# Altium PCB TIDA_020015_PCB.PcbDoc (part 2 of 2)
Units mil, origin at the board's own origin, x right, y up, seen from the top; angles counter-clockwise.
Board outline 1470 x 1510 mil, 2 copper layers (Top Layer, Bottom Layer), stack 62 mil thick; 90 components, 41 nets, 222 pads, 53 vias.
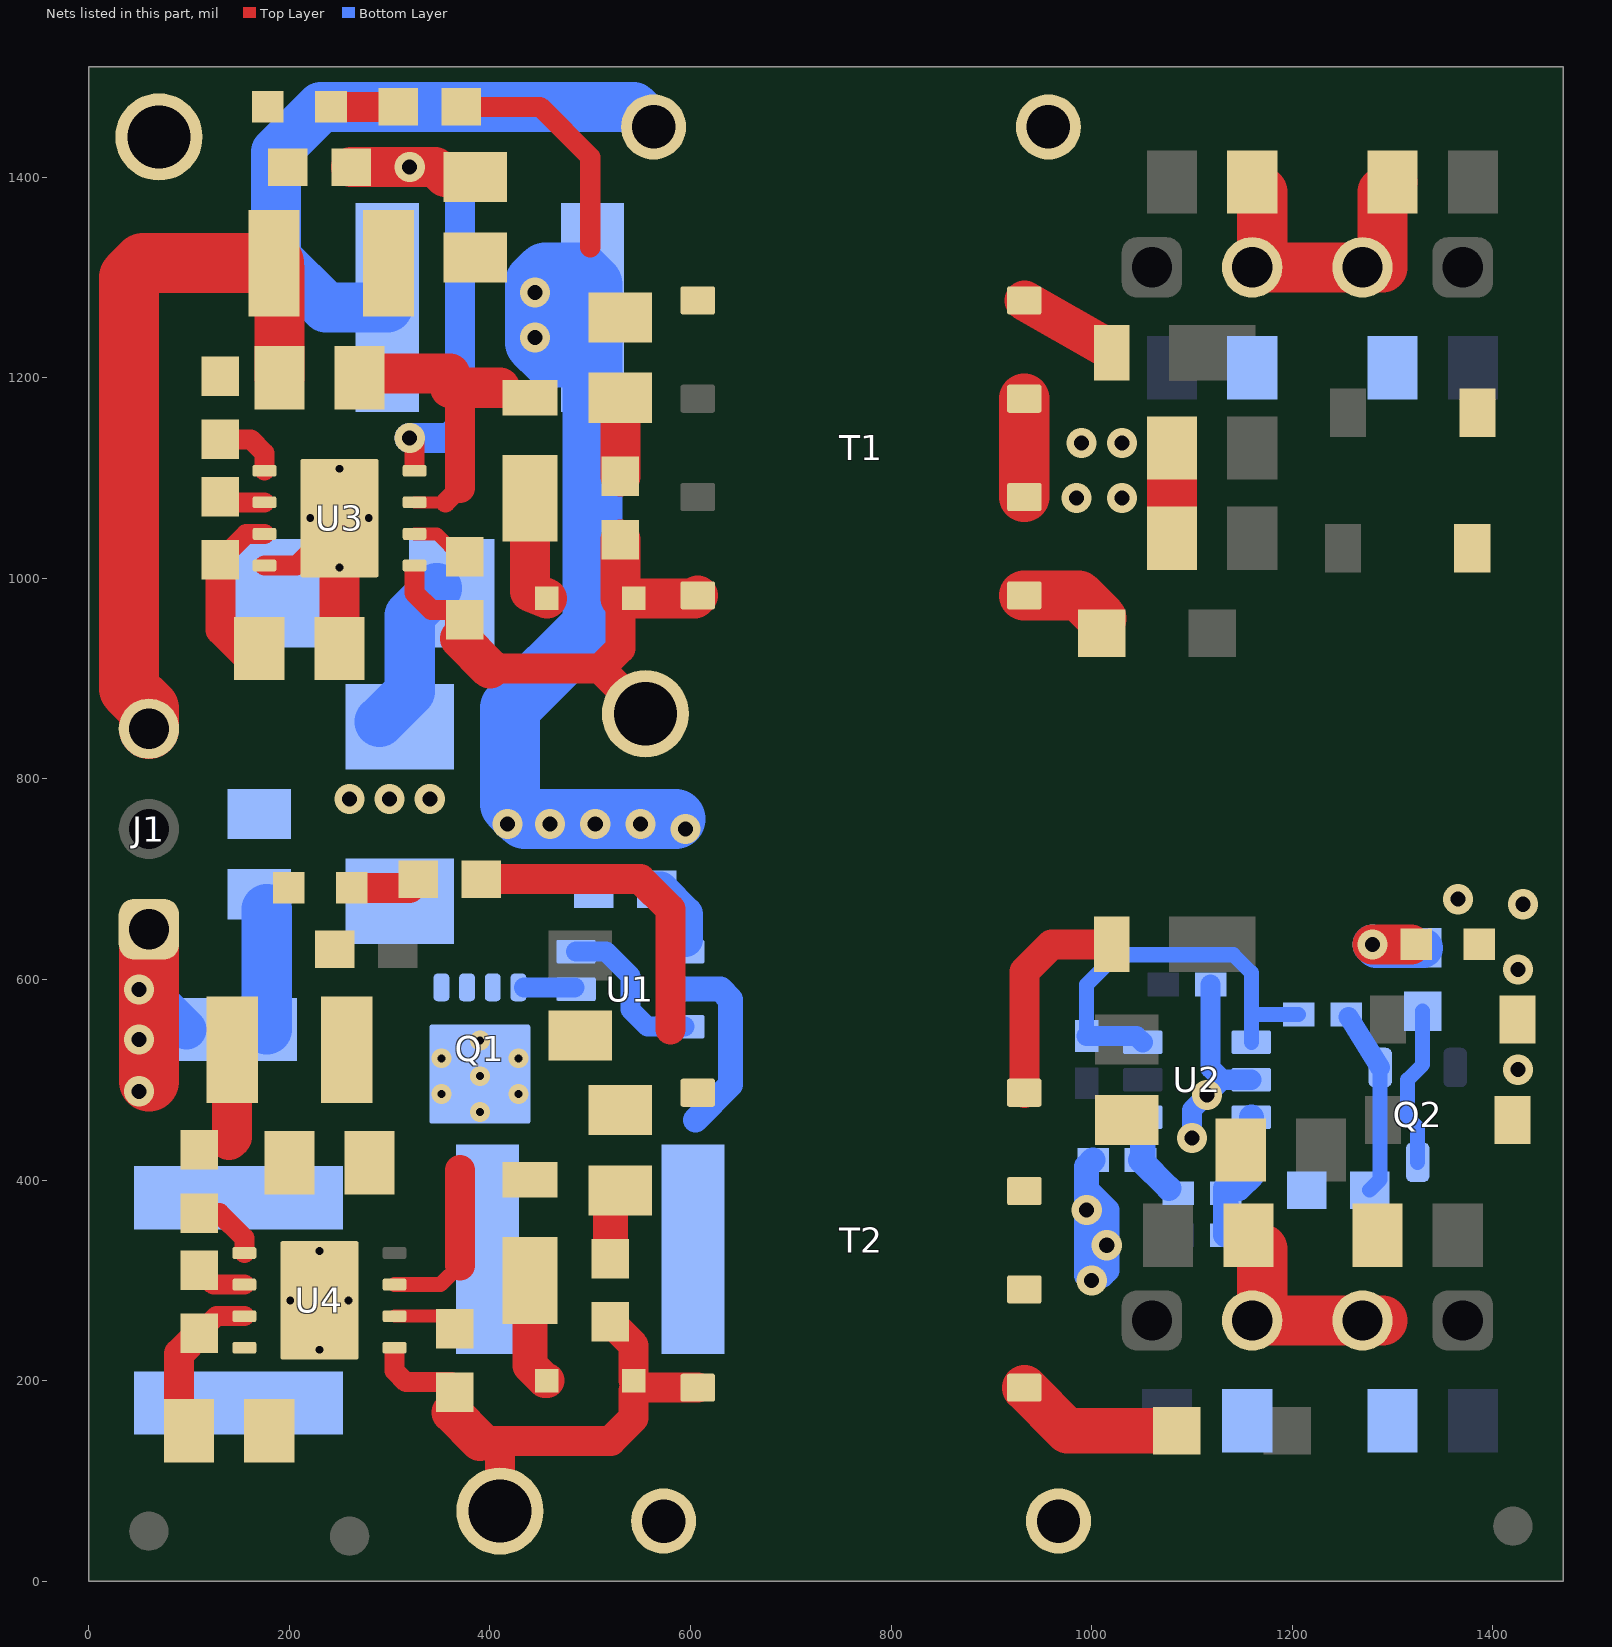
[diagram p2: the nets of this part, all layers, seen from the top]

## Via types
v1: diameter 30, hole 15, Top Layer to Bottom Layer, 38 vias
v2: diameter 19.68, hole 7.87, Top Layer to Bottom Layer, 15 vias

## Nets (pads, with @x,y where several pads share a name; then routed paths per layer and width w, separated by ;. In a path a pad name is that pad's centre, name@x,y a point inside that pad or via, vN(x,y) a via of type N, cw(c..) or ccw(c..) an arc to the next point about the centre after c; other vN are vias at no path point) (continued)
EN_U: R7.1 R14.2 U3.4 | length 487.6
  Top Layer w15: v1(320,1140) v1@324.8,1135.2
  Top Layer w20: U3.4@324.8,1112 v1@324.8,1135.2
  Top Layer w40: R14.2@261.5,1410 v1(320,1410) 345.4,1410 R7.1@355.4,1400
  Bottom Layer w30: v1@311.02,1410 v1(320,1410) 346.86,1410 370,1386.86 370,1150 360,1140 v1(320,1140)
FB_L: R20.1 U4.2 | length 58.1
  Top Layer w13: U4.2@304.8,264.25 R20.1@358.98,264.25
  Top Layer w20: R20.1@360,254.45 R20.1@362.76,251.69
FB_U: R10.1 U3.2 | length 54.6
  Top Layer w13: U3.2@324.8,1044.25 347.24,1044.25 R10.1@370,1021.5
ISO_GND_L: C16.2 C18.2 C27.2 C28.2 C29.2 C30.1 C31.1 C32.1 C34.1 D10.1 D14.2 D17.1 J7.2 J8.2 R13.1 T2.6 T2.7 U2.2 | length 611.3
  Top Layer w50: C28.2@1170,331.22 1170,260 J8.2@1289.99,260
  Bottom Layer w20: v1(1100,442.13) 1100,470 v1(1115,485) 1130,500 ; C18.2@1118.62,595 1118.62,511.38 1130,500 ; U2.2@1159.13,500 1130,500
  Bottom Layer w25: 1000,385 1015,370 v1(1015,335) 1015,310 1010,305 995,305 v1(995,370) 995,413.62 R13.1@1001.38,420
  other v1: 1000,300 1425,510 1425,610 1430,675 1365,680
ISO_GND_U: C10.2 C11.2 C12.2 C13.1 C14.1 C15.1 C19.1 D6.2 D9.1 J5.2 J6.2 T1.6 T1.7 | length 486.3
  Top Layer w50: T1.6@932.8,1080.98 T1.7@932.8,1179.02 ; C13.1@1080,1040 C10.2@1080,1130 ; C11.2@1160,1395 1170,1385 1170,1310 1290,1310 1290,1385 C14.1@1300,1395
  other v1: 985,1080 1030,1080 990,1135 1030,1135
NetC1_2: C1.2 C2.2 | length 120
  Bottom Layer w50: C1.2@177.48,550 C2.2@177.48,670
NetC3_1: C3.1 U1.1 | length 63.9
  Bottom Layer w35: C3.1@566.5,690 570,690 595,665 595,640
NetC9_1: C9.1 R2.1 | length 78.5
  Top Layer w40: C9.1@530,1101.5 R2.1@530,1180
NetC16_1: C16.1 Q2.1 R6.2 | length 186.1
  Bottom Layer w15: C16.1@1277.16,390 1287.6,400.44 Q2.1@1287.6,512.24
  Bottom Layer w20: R6.2@1256.02,562.76 Q2.1@1287.6,512.24
NetC26_1: C26.1 R17.1 | length 58.2
  Top Layer w35: C26.1@520,321.5 R17.1@520,379.7
NetD1_2: D1.2 D2.2 | length 156.6
  Bottom Layer w50: D1.2@290,857.01 320,887.01 320,962.99 D2.2@347.01,990
NetD3_1: D3.1 D7.1 | length 111.1
  Top Layer w40: D3.1@440,1079.8 440,986.69 D7.1@456.69,980
NetD4_2: D4.2 R1.1 | length 67
  Top Layer w30: D4.2@241.5,1470 R1.1@308.5,1470
NetD5_2: D5.2 T1.8 | length 94.7
  Top Layer w40: T1.8@932.8,1277.05 D5.2@1015,1230
NetD8_1: D8.1 T1.5 | length 86.6
  Top Layer w50: T1.5@932.8,982.95 986.93,982.95 D8.1@1009.88,960
NetD10_2: D10.2 R9.1 | length 90
  Top Layer w40: v1(1280,635) D10.2@1318.5,635
  Bottom Layer w40: v1(1280,635) 1283.5,631.5 R9.1@1330,631.5
NetD11_1: D11.1 D15.1 | length 107.7
  Top Layer w35: D11.1@440,299.8 440,215 455,200 D15.1@456.69,200
NetD12_2: D12.2 R16.1 | length 69.9
  Top Layer w30: D12.2@262.24,691.32 319.82,691.32 R16.1@328.5,700
NetD13_2: D13.2 T2.8 | length 219
  Top Layer w30: T2.8@932.8,487.05 932.8,607.8 960,635 D13.2@1019.8,635
NetD16_1: D16.1 T2.5 | length 169.9
  Top Layer w45: T2.5@932.8,192.95 975.75,150 D16.1@1084.88,150
NetQ1_4: Q1.4 U1.5 | length 50
  Bottom Layer w20: Q1.4@434.07,592.01 U1.5@484.12,592.05
NetQ2_3: Q2.3 R9.2 | length 161.4
  Bottom Layer w15: Q2.3@1325,417.76 1325,452.04 1314.63,462.42 1314.63,489.49 1314.78,489.65 1314.78,491.48 1315,491.69 1315,500 1330,515 R9.2@1330,568.5
NetR4_2: R4.2 R6.1 U2.1 U2.6 | length 410.2
  Bottom Layer w15: R4.2@995,543.62 995,595 1024.63,624.63 1141.21,624.63 1159.13,606.7 1159.13,555 U2.1@1159.13,537.4 ; 1159.13,565 R6.1@1206.38,565
  Bottom Layer w20: R4.2@995,543.62 1044.65,543.62 U2.6@1050.87,537.4
NetR5_1: R5.1 R8.2 U2.3 | length 135.9
  Bottom Layer w25: R5.1@1133.62,345 1133.62,391.81 1146.81,391.81 1159.13,404.13 U2.3@1159.13,462.6
NetR8_1: R8.1 R13.2 U2.4 | length 83.4
  Bottom Layer w25: U2.4@1050.87,462.6 1050.87,422.24 R13.2@1048.62,420 R8.1@1076.81,391.81
PGND: C2.1 C5.2 C6.2 C7.2 C8.2 C19.2 C20.2 C22.2 C24.2 C25.2 C34.2 C35.2 D2.1 D4.1 D12.1 J1.3 R14.1 R15.1 R23.1 R24.1 TP2.1 U1.2 U3.8 U3.9@250,1060 U4.8 U4.9@230,280 | length 1873.9
  Top Layer w20: U3.8@175.2,1012.76 207.24,1012.76 U3.9@250,1055.51
  Top Layer w30: U3.9@250,1055.51 U3.9@250,1060
  Top Layer w40: 140,440 142.91,442.91 C24.2@142.91,530 ; C7.2@184.65,1314.3 C7.2@190,1308.94 ; R15.1@250,920 U3.9@250,1055.51
  Top Layer w50: C8.2@190,1200 C7.2@190,1308.94
  Top Layer w60: J1.3@60,850 60,870 40,890 40,1300 54.3,1314.3 C7.2@184.65,1314.3
  Bottom Layer w25: U1.2@594.13,590.3 629.7,590.3 640,580 640,495 605,460
  Bottom Layer w50: C6.2@297.64,1270 236.61,1270 186.61,1320 186.61,1424.96 231.65,1470 543.15,1470 C19.2@563.15,1450
  other v1: 260,780 300,780 340,780
  other v2: 230,230.79 200.87,280 259.13,280 230,329.21 250,1010.79 220.87,1060 279.13,1060 250,1109.21
RSET_L: R21.2 R24.2 U4.7 | length 161.8
  Top Layer w20: R21.2@110,247 127.25,264.25 U4.7@155.2,264.25
  Top Layer w30: R24.2@100,150 90,160 90,227 R21.2@110,247
RSET_U: R11.2 R15.2 U3.7 | length 175.1
  Top Layer w20: R11.2@131.3,1018.5 156.73,1043.94 175.2,1043.94 U3.7@175.2,1044.25
  Top Layer w30: R11.2@131.3,1018.5 131.3,948.7 160,920 R15.2@170,920
SS_L: C35.1 U4.5 | length 70.3
  Top Layer w20: C35.1@110,367 130.2,367 155.2,342 U4.5@155.2,327.24
SS_U: C20.1 U3.5 | length 67.1
  Top Layer w20: C20.1@131.3,1138.5 161.5,1138.5 175.2,1124.8 U3.5@175.2,1107.24
SW_L: C26.2 D15.2 R20.2 T2.4 TP3.1 U4.1 | length 527.5
  Top Layer w20: 304.8,225 304.8,209.84 316.14,198.5 R20.2@361.73,198.5
  Top Layer w30: 361.73,168.27 R20.2@361.73,190 ; 390,140 410,140 ; TP3.1@410,70 410,140 ; C26.2@520,258.5 543.31,235.2 D15.2@543.31,200 ; D15.2@543.31,190 543.31,162.81 520.5,140 410,140 ; D15.2@546.26,192.95 T2.4@607.2,192.95
  Top Layer w40: 361.73,168.27 390,140
SW_U: C9.2 D7.2 R10.2 T1.4 TP1.1 U3.1 | length 516.6
  Top Layer w20: U3.1@324.8,1007 324.8,985.2 341.5,968.5 R10.2@370,968.5
  Top Layer w30: R10.2@370,940.02 R10.2@370,958.5 ; 400.02,910 510,910 ; 530,980 530,930 510,910 ; TP1.1@550,870 510,910
  Top Layer w40: R10.2@370,940.02 400.02,910 ; C9.2@530,1038.5 530,980 604.25,980 T1.4@607.2,982.95
TC_L: R21.1 U4.6 | length 51.1
  Top Layer w20: R21.1@110,310 124.25,295.75 U4.6@155.2,295.75
TC_U: R11.1 U3.6 | length 46.3
  Top Layer w20: R11.1@131.3,1081.5 137.05,1075.75 U3.6@175.2,1075.75
Vin: C6.1 C7.1 C8.1 C22.1 C24.1 C25.1 D3.2 D11.2 Q1.5 Q1.6 Q1.7 Q1.8 Q1.9@390,505.63 R1.2 R2.2 R7.2 R16.2 R17.2 R19.2 T1.1 T2.1 U1.4 U3.3 U4.3 | length 1924.3
  Top Layer w12: U3.3@324.8,1075.75 355.75,1075.75
  Top Layer w15: U4.3@304.8,295.75 350.75,295.75 370,315
  Top Layer w20: 355.75,1075.75 370,1090 ; R1.2@371.5,1470 450,1470 500,1420 500,1330
  Top Layer w30: 370,315 370,410 ; 370,1090 370,1190 ; R16.2@391.5,700 550,700 580,670 580,550
  Top Layer w40: C8.1@280,1204.3 360,1204.3 ; 360,1190 370,1190 410.2,1190
  Bottom Layer w60: 499.45,950.27 420,870.81 420,775 435,760 v1@585,760 ; 502.36,947.36 C6.1@502.36,1220 ; C6.1@502.36,1220 C6.1@502.36,1270 502.36,1292.64 490,1305 455.26,1305 445,1294.74 v1(445,1285) v1(445,1240) 445,1235 460,1220 C6.1@502.36,1220
  other v1: 595,750 417.5,755 460,755 505,755 550,755
  other v2: 390,467.93 351.61,485.75 428.39,485.75 390,503.56 351.61,521.38 428.39,521.38 390,539.19
Vin_Pri: C1.1 C3.2 C5.1 D1.1 J1.1 Q1.1 Q1.2 Q1.3 U1.3 U1.6 | length 347
  Top Layer w60: v1@60,498.5 J1.1@60,630
  Bottom Layer w20: U1.6@485.87,627.7 515.84,627.7 540,603.54 540,570 557.1,552.9 U1.3@594.13,552.9
  Bottom Layer w40: v1@57.48,590 C1.1@97.48,550
  other v1: 50,488.5 50,540 50,590
pads on no net: FID1.1 FID2.1 FID3.1 J1.2 Q1.9@351.61,484.76 Q1.9@363.92,503.56 Q1.9@363.92,539.19 Q1.9@377.2,484.76 Q1.9@390,518.13 Q1.9@402.8,484.76 Q1.9@416.08,503.56 Q1.9@416.08,539.19 Q1.9@428.39,484.76 T1.2 T1.3 T2.2 T2.3 U3.9@250,1030.28 U3.9@250,1089.72 U4.9@230,250.28 U4.9@230,309.72

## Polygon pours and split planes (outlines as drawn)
PGND on Top Layer "TOP_LAYER_PGND_P004" (solid, remove dead copper, pour order 4): 91.15,1261.15 230,1261.15 230,1510 0,1510 0,770 40,730 70,730 130,790 130,1135.55 94.45,1135.55 70,1160 70,1240 90,1260
PGND on Top Layer "TOP_LAYER_PGND_P002" (solid, remove dead copper, pour order 2): 210,1240 230,1220 230,1180 290,1140 290,1070 290,1000 280,990 280,910 270,900 130,900 100,930 100,1230 110,1240
Vin on Top Layer "TOP_LAYER_VIN_P000" (solid, remove dead copper, pour order 0): 330.82,1367.44 348.27,1350 572.52,1350 630,1292.52 630,1250 610,1230 480,1230 459.5,1209.5 459.5,1160 449.5,1150 360,1150 360,1090 340,1070 310,1070 310,1130 290,1150 260,1150 250,1160 250,1360 257.44,1367.44
PGND on Top Layer "TOP_LAYER_PGND_P008" (solid, remove dead copper, pour order 8): 217.24,460 230,447.24 230,378.33 270,351.67 270,290 270,220 260,210 260,130 220,90 110,90 80,120 80,450 90,460
PGND on Top Layer "TOP_LAYER_PGND_P010" (solid, remove dead copper, pour order 10): 280,890 350,820 350,496.93 323.07,470 30,470 0,500 0,880 20,890
Vin on Top Layer "TOP_LAYER_VIN_P012" (solid, remove dead copper, pour order 12): 590,770 625,735 625,383.86 616.14,375 263.27,375 230,408.27 230,590 410,770
ISO_GND_U on Top Layer "TOP_LAYER_ISO_GND_U_P018" (solid, remove dead copper, pour order 18): 985,1160 1105,1160 1105,1005 1055,1005 1005,1055 926.14,1055 910,1071.14 915,1076.14 915,1195 950,1195
ISO_GND_U on Top Layer "TOP_LAYER_ISO_GND_U_P022" (solid, remove dead copper, pour order 22): 1470,1505 1465,1510 1460,1505 910,1505 910,955 930,935 1420,935 1470,985
+15V_Iso_L on Top Layer "TOP_LAYER_+15V_ISO_L_P024" (solid, remove dead copper, pour order 24): 1315,515 1335,535 1335,652.72 1302.72,685 1029.66,685 1000,655.34 1000,521.81 1006.81,515
ISO_GND_L on Top Layer "TOP_LAYER_ISO_GND_L_P026" (solid, remove dead copper, pour order 26): 1475,695 1470,700 1465,695 915,695 915,35 950,0 1435,0 1475,40
Vin_Pri on Bottom Layer "BOTTOM_LAYER_VIN_PRI_P006" (solid, remove dead copper, pour order 6): 190,680 240,730 397.27,730 410,717.27 511.58,717.27 530,698.85 530,571.48 500,541.48 500,540 460,540 460,560 437.01,582.99 312.99,582.99 287.24,557.24 287.24,384.61 252.64,350 10,350 0,360 0,670 10,680
Vin on Bottom Layer "BOTTOM_LAYER_VIN_P014" (solid, remove dead copper, pour order 14): 510,565 520,555 520,250 495,225 363.03,225 340,248.03 340,555 350,565
PGND on Bottom Layer "BOTTOM_LAYER_PGND_P016" (solid, pour order 16): 635,1510 635,20 615,0 5,0 5,1510
ISO_GND_U on Bottom Layer "BOTTOM_LAYER_ISO_GND_U_P020" (solid, remove dead copper, pour order 20): 1470,1505 1465,1510 1460,1505 910,1505 910,955 930,935 1420,935 1470,985
ISO_GND_L on Bottom Layer "BOTTOM_LAYER_ISO_GND_L_P028" (solid, remove dead copper, pour order 28): 1475,695 1470,700 1465,695 915,695 915,35 950,0 1435,0 1475,40

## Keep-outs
Keep-Out Layer:
  text ".Layer_Name" at 577,-858.49 h60

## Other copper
Top Layer:
  text ".Layer_Name" at 577,-858.49 h60
Bottom Layer:
  pour cut-out: 546.39,937 554.38,945 620,945 640,935 640,780 645,775 640,770 620,770 546.39,843.61
  text ".Layer_Name" at 577,-858.49 h60

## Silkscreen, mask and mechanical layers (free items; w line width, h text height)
Top Overlay:
  lines w10: 0,750 0,0 1470,0 1470,750 ; 0,760 0,1510 795,1510 ; 250,750 585,750 ; 620,750 1370,750 ; 1030,1510 1125,1510 ; 1190,1510 1470,1510 1470,760
  text "SW_U" at 640,860 h45
  text "'.PRJ_Number'.PCB_Rev" at 710,780 h60
  text "Vcc2 GND" at 140,620 h60 r90
  text "SW_L" at 465,125 h45
  text ".Layer_Name" at 577,-858.49 h60
Bottom Overlay:
  lines w10: 15,1185 240,1185 ; 275,1185 460,1185 ; 475,650 615,650 655,610 925.26,610 ; 545,1140 545,1020 620,945 620,895 1470,895 ; 929.13,613.88 929.13,659.13 ; 930.34,660.34 1055.34,660.34 1110,715 ; 1115,720 1470,720
  text "VEE2U SU SU Vcc2U" at 1435,1385 h50
  text "VEE2L SL SL Vcc2L" at 1430,65 h50
  text ".Layer_Name" at 577,-858.49 h60
Top Paste:
  text ".Layer_Name" at 577,-858.49 h60
Bottom Paste:
  text ".Layer_Name" at 577,-858.49 h60
Top Solder:
  text ".Layer_Name" at 577,-858.49 h60
  text ".Layer_Name" at 577,-858.49 h60
Bottom Solder:
  text ".Layer_Name" at 577,-858.49 h60
Drill Guide:
  text ".Layer_Name" at 577,-858.49 h60
M1 Board Outline:
  the board outline again, w10
  text ".Layer_Name" at 577,-858.49 h60
M2 Board Dimensions:
  rectangle: 125,-400 500,-275
  rectangle: 0,-275 125,-150
  lines w7: 0,-275 1000,-275 ; 125,-400 125,-150 ; 250,-400 250,-150 ; 500,-400 500,-150 ; 750,-400 750,-150 ; 0,-400 0,-150 1000,-150 1000,-400 0,-400
  text ".Layer_Name" at 577,-858.49 h60
M3 3D STEP Top:
  text ".Layer_Name" at 577,-858.49 h60
M4 3D STEP Bottom:
  text ".Layer_Name" at 577,-858.49 h60
M5 Assembly Top:
  lines w10: -292,-930.17 6308,-930.17 ; -292,-726.83 6310,-726.83 ; -292,-523.5 -292,-1133.5 3713,-1133.5 6310,-1133.5 6310,-523.5 -291.5,-523.5 -291.5,-1133.5 1284,-1133.5 ; 2173,-1133.5 2173,-523.5 ; 3440,-726.83 3440,-523.5 ; 4280,-726.83 4280,-523.5 ; 4902,-1140 4902,-937.17
  text "COMPONENTS MARKED 'DNP' SHOULD NOT BE POPULATED." at 1153.5,-318.5 h60
  text "ASSEMBLY VARIANT:" at 1153,-434 h60
  text ".VariantName" at 2189,-434 h60
  text "PCB VIEWED FROM TOP SIDE" at -228.5,-655.67 h60
  text "BOARD #:" at 2248,-655.67 h60
  text ".PRJ_Number" at 2793.5,-655.67 h60
  text "REV:" at 3638,-655.67 h60
  text ".PCB_Rev" at 3929.5,-655.67 h60
  text "SVN REV:" at 4476,-655.67 h60
  text ".VersionControl_RevNumber" at 4982,-655.67 h60
  text "TID #:" at 2248,-859 h60
  text ".TID" at 2793.5,-859 h60
  text "PLOT NAME =" at -228.5,-1064.34 h60
  text ".plot_File_Name" at 577,-1064.34 h60
  text "GENERATED    :" at 2250,-1064.34 h60
  text ".Print_Date" at 3119.5,-1064.34 h60
  text ".Print_Time" at 3848.5,-1064.34 h60
  text "TEXAS INSTRUMENTS" at 5113,-1064.34 h60
M6 Assembly Bottom:
  lines w10: -292.5,-727.33 6309.5,-727.33 ; -290.5,-930.67 6309.5,-930.67 ; 1115.5,-1140.5 1115.5,-937.67 ; 1737.5,-727.33 1737.5,-524 ; 2577.5,-727.33 2577.5,-524 ; 3844.5,-1134 3844.5,-524 ; 4733.5,-1134 6309,-1134 6309,-524 -292.5,-524 -292.5,-1134 2304.5,-1134 6309.5,-1134 6309.5,-524
  text "COMPONENTS MARKED 'DNP' SHOULD NOT BE POPULATED." at 6102,-318 h60
  text ".VariantName" at 5058,-434 h60
  text "ASSEMBLY VARIANT:" at 6097,-434 h60
  text ".VersionControl_RevNumber" at 1035.5,-656.17 h60
  text "SVN REV:" at 1541.5,-656.17 h60
  text ".PCB_Rev" at 2088,-656.17 h60
  text "REV:" at 2379.5,-656.17 h60
  text ".PRJ_Number" at 3224,-656.17 h60
  text "BOARD #:" at 3769.5,-656.17 h60
  text "PCB VIEWED FROM BOTTOM SIDE" at 6246,-656.17 h60
  text ".TID" at 3224,-859.5 h60
  text "TID #:" at 3769.5,-859.5 h60
  text "TEXAS INSTRUMENTS" at 904.5,-1064.84 h60
  text ".Print_Time" at 2169,-1064.84 h60
  text ".Print_Date" at 2898,-1064.84 h60
  text "GENERATED    :" at 3767.5,-1064.84 h60
  text ".plot_File_Name" at 5440.5,-1064.84 h60
  text "PLOT NAME =" at 6246,-1064.84 h60
M9 Title Sheet:
  drawing of 57 lines, arcs and shapes, not listed
  text "1" at 739.84,8036.5 h70
  text "2" at 3235.5,8036.5 h70
  text "3" at 5724.84,8036.5 h70
  text "4" at 8231.51,8036.5 h70
  text "5" at 10730.5,8036.5 h70
  text "6" at 13235.5,8036.5 h70
  text "A" at -416.5,6893.5 h70
  text "A" at 14383.5,6893.5 h70
  text "B" at -416.5,4513.5 h70
  text "B" at 14383.5,4513.5 h70
  text "C" at -416.5,2138.5 h70
  text "C" at 14383.5,2138.5 h70
  text "PROJECT TITLE:" at 11343.5,277.5 h45
  text ".PRJ_Title" at 11393.5,144.17 h70
  text "DESIGNED FOR:" at 11343.5,-23.5 h45
  text ".PRJ_Customer" at 11393.5,-163.5 h70
  text "D" at -416.5,-231.5 h70
  text "D" at 14383.5,-231.5 h70
  text "FILE NAME:" at 11343.5,-323.5 h45
  text ".PCB_File_Name_No_Path" at 11393.5,-443.5 h70
  text "Texas Instruments (TI) and/or its licensors do not warrant the accuracy or completeness of this specification" at 6374,-605.34 h45
  text "ENGINEER:" at 11343.5,-613.5 h45
  text "LAYOUT BY:" at 12848.5,-613.5 h45
  text "or any information contained therein. TI and/or its licensors do not warrant that this design will meet" at 6329.01,-718 h45
  text ".PRJ_Engineer" at 11393.5,-768.49 h70
  text ".PCB_Layout" at 12899,-768.49 h70
  text "the specifications, will be suitable for your application or fit for any particular purpose, or will operate in" at 6329.01,-830.67 h45
  text ".Layer_Name" at 577,-858.49 h60
  text "ALTIUM DESIGNER VERSION:" at 12848.5,-923.5 h45
  text "an implementation. TI and/or its licensors do not warrant that the design is production worthy. You should" at 6329.01,-943.33 h45
  text "completely validate and test your design implementation to confirm the system functionality for your application." at 6374,-1056 h45
  text ".print_Scale" at 11393.5,-1056.83 h70
  text ".Application_BuildNumber" at 12899,-1056.83 h70
  text "1" at 739.84,-1263.5 h70
  text "2" at 3235.5,-1263.5 h70
  text "3" at 5724.84,-1263.5 h70
  text "4" at 8231.51,-1263.5 h70
  text "5" at 10730.5,-1263.5 h70
  text "6" at 13235.5,-1263.5 h70
M10 Fab Notes:
  drawing of 189 lines, arcs and shapes, not listed
  text "DESIGN INFORMATION" at 12382.02,6356.17 h60
  text "MIN. TRACK WIDTH:" at 11737.46,6224.05 h60
  text "8" at 12833.7,6224.05 h60
  text "MIL" at 12988.46,6224.05 h60
  text "MIN. CLEARANCE:" at 11737.46,6099.92 h60
  text "0.2" at 12773.7,6099.93 h60
  text "mm" at 12988.46,6099.92 h60
  text "MIN. VIA PAD SIZE:" at 11737.46,5975.8 h60
  text "24" at 12803.71,5975.8 h60
  text "MIL" at 12988.46,5975.8 h60
  text "0.05mm (2MIL)" at 12432.46,5845.9 h60
  text "MINIMUM ANNULAR RING" at 11408.23,5837.67 h60
  text "EXTERNAL" at 13140.46,5837.67 h60
  text "PER" at 11608.23,5727.55 h60
  text "IPC-D-275 CLASS 2 LEVEL C" at 11828.23,5727.54 h60
  text "MIL, HOLES" at 13316.46,5627.07 h60
  text "+/-" at 12924,5618.48 h60
  text "+/-" at 13778,5618.48 h60
  text "REGISTRATION TOLERANCES:" at 11408.23,5617.42 h60
  text "METAL" at 12608,5617.42 h60
  text "5" at 13184.2,5617.42 h60
  text "3" at 14017.2,5617.42 h60
  text "MIL" at 14133.46,5617.42 h60
  text "HOLE SIZE TOLERANCE (UNLESS OTHERWISE SPECIFIED):" at 11408.23,5519.1 h60
  text "+/-" at 13778,5516.23 h60
  text "3" at 14017.2,5515.17 h60
  text "MIL" at 14133.46,5515.17 h60
  text "MATERIAL:" at 11333.46,5377.52 h60
  text "FR-4 High Tg" at 12319.9,5249 h60
  text "X" at 12175.46,5241.01 h60
  text "FR-408" at 11754.46,5236.49 h60
  text "OTHER" at 13242.46,5236.49 h60
  text "62 MIL (1.6mm) +/-10%" at 12074.56,5093.46 h60
  text "X" at 11954.46,5091.01 h60
  text "THICKNESS:" at 11408.23,5085.24 h60
  text "OTHER" at 13359.46,5085.24 h60
  text "TOLERANCE:" at 11408.23,4946.92 h60
  text "X" at 12256.46,4946.92 h60
  text "ANSI IPC-6012 TYPE 3 CLASS 2" at 12434.48,4946.92 h60
  text "OTHER +/-" at 12434.46,4802.73 h60
  text "BOW & TWIST:" at 11408.23,4657.54 h60
  text "X" at 12256.46,4657.54 h60
  text "ANSI IPC-6012 TYPE 3 CLASS 2" at 12434.48,4657.54 h60
  text "OTHER +/-" at 12434.46,4510.85 h60
  text "DRILLING:" at 11333.46,4380.23 h60
  text "NC_DRILL FILES" at 13094.46,4275.04 h60
  text "REFERENCE:" at 11408.23,4271.1 h60
  text "X" at 12065.46,4271.01 h60
  text "AS SHOWN" at 12243.46,4271.1 h60
  text "X" at 12966.46,4271.1 h60
  text "OTHER" at 13392.46,4128.85 h60
  text "PTH COPPER THICKNESS:" at 11407.91,4125.32 h60
  text "X" at 12547.14,4125.32 h60
  text "20-30 um" at 12675.14,4125.32 h60
  text "BOARD FINISH:" at 11333.46,3977.73 h60
  text "SILKSCREEN:" at 11488.68,3867.6 h60
  text "X" at 12446.46,3867.6 h60
  text "TOP" at 12563.46,3867.6 h60
  text "X" at 12956.46,3867.6 h60
  text "BOTTOM" at 13074.46,3867.6 h60
  text "SILKSCREEN COLOR:" at 11488.68,3712.41 h60
  text "X" at 12445.46,3712.41 h60
  text "WHITE" at 12563.46,3712.41 h60
  text "OTHER" at 13074.46,3712.41 h60
  text "X" at 12576.46,3568.96 h60
  text "GREEN" at 12694.46,3568.96 h60
  text "OTHER" at 13312.46,3568.96 h60
  text "SOLDER RESIST COLOR:" at 11488.68,3562.1 h60
  text "X" at 12576.46,3414.71 h60
  text "MATTE" at 12694.46,3414.71 h60
  text "SEMI-GLOSS" at 13312,3414.07 h60
  text "IMMERSION GOLD (ENIG)" at 12394.46,3241.94 h60
  text "ENEPIG" at 13732,3234.72 h60
  text "SURFACE FINISH:" at 11333.46,3233.72 h60
  text "X" at 12216.46,3233.72 h60
  text "IMM. TIN/SILVER OR EQUIV" at 11663,3096.4 h60
  text "OTHER" at 13094.46,3092.47 h60
  text "ARRAY/PANEL:" at 11333.46,2937.09 h60
  text "CUT AND TRIM PER M1 BOARD OUTLINE" at 12394.46,2928.87 h60
  text "N.C. ROUTE" at 12394.46,2792.9 h60
  text "X" at 13082.46,2792.9 h60
  text "V. SCORE" at 13260.46,2792.9 h60
  text "CERTIFICATION:" at 11333.46,2663.77 h60
  text "MATERIALS AND WORKMANSHIP FOR ALL PCBS" at 12058.46,2663.77 h60
  text "TO MEET OR EXCEED THE REQUIREMENTS OF:" at 12058.46,2569.71 h60
  text "X" at 11695.97,2441.08 h60
  text "ANSI IPC-A-600F CLASS ->" at 11823.96,2441.08 h60
  text "X" at 13471.97,2441.08 h60
  text "2" at 13581.96,2441.08 h60
  text "1" at 13266.96,2439.58 h60
  text "3" at 13935.96,2439.58 h60
  text "X" at 12507.97,2293.39 h60
  text "RoHS" at 12635.96,2293.39 h60
  text "OTHER" at 13280.36,2293.39 h60
  text "PER ORDER" at 13677.42,2293.39 h60
  text "ALL BOARDS MUST MEET OR EXCEED UL94-V0 REQUIREMENTS." at 11361,2139.57 h60
  text "PCB MUST BEAR THE UL94V-0 UL REGISTERED MATERIAL ID NUMBER" at 11361,2023.5 h60
  text "ADDITIONAL REQUIREMENTS:" at 11333.46,1854.08 h60
  text "MICROSECTION:" at 11408.23,1746.95 h60
  text "YES" at 12313.96,1746.95 h60
  text "REQUIRED" at 13175.46,1602.62 h60
  text "BARE BOARD ELEC. TEST:" at 11408.23,1599.76 h60
  text "NONE" at 12713.96,1599.76 h60
  text "X" at 13057.46,1599.76 h60
  text "PER ORDER" at 13767.46,1599.76 h60
  text "XX MIL VIAS REQUIRE NON-CONDUCTIVE FILL AND PLANARIZE" at 11576.38,1394.82 h59
  text "XX MIL VIAS REQUIRE CONDUCTIVE FILL AND PLANARIZE" at 11584.38,1290.84 h60
  text "OUTER XX MIL TRACES REQUIRE 50 OHM SINGLE-ENDED IMPEDANCE" at 11583.39,1127.46 h58
  text "LAYER 2 & 3 (INNER LAYERS) XX MIL WIDE, XX MIL SPACE / TRACES REQUIRE 100 OHM DIFFERENTIAL IMPEDANCE" at 11575.39,891.74 h60
  text ".Layer_Name" at 577,-858.49 h60
M11 Gerber Information:
  lines w10: -292,-930.17 6308,-930.17 ; -292,-726.83 6310,-726.83 ; -292,-523.5 -292,-1133.5 3713,-1133.5 6310,-1133.5 6310,-523.5 -291.5,-523.5 -291.5,-1133.5 1284,-1133.5 ; 2173,-1133.5 2173,-523.5 ; 3440,-726.83 3440,-523.5 ; 4280,-726.83 4280,-523.5 ; 4902,-1140 4902,-937.17
  text "ALL ARTWORK VIEWED FROM TOP SIDE" at -228.5,-655.67 h60
  text "BOARD #:" at 2248,-655.67 h60
  text ".PRJ_Number" at 2793.5,-655.67 h60
  text "REV:" at 3638,-655.67 h60
  text ".PCB_Rev" at 3929.5,-655.67 h60
  text "SVN REV:" at 4476,-655.67 h60
  text ".VersionControl_RevNumber" at 4982,-655.67 h60
  text "LAYER NAME =" at -228.5,-858.49 h60
  text "TID #:" at 2248,-859 h60
  text ".TID" at 2793.5,-859 h60
  text "PLOT NAME =" at -228.5,-1064.34 h60
  text ".plot_File_Name" at 577,-1064.34 h60
  text "GENERATED    :" at 2250,-1064.34 h60
  text ".Print_Date" at 3119.5,-1064.34 h60
  text ".Print_Time" at 3848.5,-1064.34 h60
  text "TEXAS INSTRUMENTS" at 5113,-1064.34 h60
M12 Stackup:
  drawing of 191 lines, arcs and shapes, not listed
  text "Layer" at 9797.84,7830 h60
  text "Name" at 10207.76,7830 h60
  text "Material" at 11137.5,7830 h60
  text "Thickness" at 11997.27,7830 h60
  text "Constant" at 12647.1,7830 h60
  text "Board Layer Stack" at 13216.96,7830 h60
  text "1" at 9797.84,7710 h60
  text "Top Overlay" at 10207.76,7710 h60
  text "2" at 9797.84,7590 h60
  text "Top Solder" at 10207.76,7590 h60
  text "Solder Resist" at 11137.5,7590 h60
  text "0.40mil" at 11997.27,7590 h60
  text "3.5" at 12647.1,7590 h60
  text "3" at 9797.84,7470 h60
  text "Top Layer" at 10207.76,7470 h60
  text "Copper" at 11137.5,7470 h60
  text "1.40mil" at 11997.27,7470 h60
  text "4" at 9797.84,7350 h60
  text "Dielectric1" at 10207.76,7350 h60
  text "FR-4" at 11137.5,7350 h60
  text "59.20mil" at 11997.27,7350 h60
  text "4.8" at 12647.1,7350 h60
  text "5" at 9797.84,7230 h60
  text "Bottom Layer" at 10207.76,7230 h60
  text "Copper" at 11137.5,7230 h60
  text "1.40mil" at 11997.27,7230 h60
  text "6" at 9797.84,7110 h60
  text "Bottom Solder" at 10207.76,7110 h60
  text "Solder Resist" at 11137.5,7110 h60
  text "0.40mil" at 11997.27,7110 h60
  text "3.5" at 12647.1,7110 h60
  text "7" at 9797.84,6990 h60
  text "Bottom Overlay" at 10207.76,6990 h60
  text ".Layer_Name" at 577,-858.49 h60
M13 Component Bodies Top:
  text ".Layer_Name" at 577,-858.49 h60
M14 Component Bodies Bottom:
  text ".Layer_Name" at 577,-858.49 h60
M15 Courtyards Top:
  text ".Layer_Name" at 577,-858.49 h60
M16 Courtyards Bottom:
  text ".Layer_Name" at 577,-858.49 h60
Drill Drawing:
  circle w10: c5363.72,3141.96 r27.63
  lines w10: 5336.09,2755.19 5349.9,2755.19 5363.72,2741.38 5377.53,2755.19 5391.34,2755.19 5377.53,2769 5391.34,2782.82 5377.53,2782.82 5363.72,2796.63 5349.9,2782.82 5336.09,2782.82 5349.9,2769 5336.09,2755.19 ; 5336.09,2865.7 5363.72,2879.51 5391.34,2865.7 5377.53,2893.32 5391.34,2920.95 5363.72,2907.14 5336.09,2920.95 5349.9,2893.32 5336.09,2865.7 ; 5336.09,2990.02 5391.34,2990.02 5391.34,3045.27 5336.09,3045.27 5336.09,2990.02 ; 5336.09,3252.47 5349.9,3252.47 5349.9,3238.66 5377.53,3238.66 5377.53,3252.47 5391.34,3252.47 5391.34,3280.1 5377.53,3280.1 5377.53,3293.91 5349.9,3293.91 5349.9,3280.1 5336.09,3280.1 5336.09,3252.47
  lines w12: 5286,2704.08 8517.49,2704.08 ; 5286,3325.68 8517.49,3325.68 ; 5623.86,2579.76 5623.86,3450 ; 5955.86,2579.76 5955.86,3450 ; 6592.43,2579.76 6592.43,3450 ; 6851.57,2579.76 6851.57,3450 ; 7226.72,2579.76 7226.72,3450 ; 7951.05,2579.76 7951.05,3450 ; 5286,2579.76 8517.49,2579.76 8517.49,3450 5286,3450 5286,2579.76
  text "Symbol" at 5360.59,3362.98 h72
  text "Quantity" at 5661.16,3362.98 h72
  text "Finished Hole Size" at 5993.16,3362.98 h72
  text "Plated" at 6629.72,3362.98 h72
  text "Hole Type" at 6888.86,3362.98 h72
  text "Drill Layer Pair" at 7264.02,3362.98 h72
  text "Hole Tolerance" at 7988.35,3362.98 h72
  text "15" at 5661.16,3238.66 h60
  text "7.87mil (0.200mm)" at 5993.16,3238.66 h60
  text "PTH" at 6629.72,3238.66 h60
  text "Round" at 6888.86,3238.66 h60
  text "Top Layer - Bottom Layer" at 7264.02,3238.66 h60
  text "38" at 5661.16,3114.34 h60
  text "15.00mil (0.381mm)" at 5993.16,3114.34 h60
  text "PTH" at 6629.72,3114.34 h60
  text "Round" at 6888.86,3114.34 h60
  text "Top Layer - Bottom Layer" at 7264.02,3114.34 h60
  text "11" at 5661.16,2990.02 h60
  text "40.16mil (1.020mm)" at 5993.16,2990.02 h60
  text "PTH" at 6629.72,2990.02 h60
  text "Round" at 6888.86,2990.02 h60
  text "Top Layer - Bottom Layer" at 7264.02,2990.02 h60
  text "4" at 5661.16,2865.7 h60
  text "43.31mil (1.100mm)" at 5993.16,2865.7 h60
  text "PTH" at 6629.72,2865.7 h60
  text "Round" at 6888.86,2865.7 h60
  text "Top Layer - Bottom Layer" at 7264.02,2865.7 h60
  text "3" at 5661.16,2741.38 h60
  text "63.00mil (1.600mm)" at 5993.16,2741.38 h60
  text "PTH" at 6629.72,2741.38 h60
  text "Round" at 6888.86,2741.38 h60
  text "Top Layer - Bottom Layer" at 7264.02,2741.38 h60
  text "71 Total" at 5661.16,2617.06 h60
  text ".Layer_Name" at 577,-858.49 h60
M17 Embedded Cavity:
  text ".Layer_Name" at 577,-858.49 h60
M18 Embedded Assembly:
  text ".Layer_Name" at 577,-858.49 h60
M19 Embedded Keepout:
  text ".Layer_Name" at 577,-858.49 h60

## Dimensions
0,0 to 1470,0 on M2 Board Dimensions
0,0 to 0,1510 on M2 Board Dimensions
0,-400 to 1000,-400 on M2 Board Dimensions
